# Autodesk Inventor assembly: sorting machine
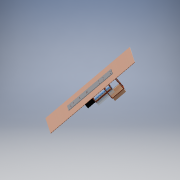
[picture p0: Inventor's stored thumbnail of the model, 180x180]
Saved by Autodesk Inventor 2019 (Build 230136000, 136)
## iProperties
Created: 2021-07
Part Number: sorting machine
Document SubType Name: Assembly
Designer: Avinash
Author: Avinash
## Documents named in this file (18)
- C:\Users\Avinash\Desktop\sorting machine\sorting machine.iam
- C:\Users\Avinash\Desktop\sorting machine\Funnel.ipt
- C:\Users\Avinash\Desktop\sorting machine\base.ipt
- C:\Users\Avinash\Desktop\sorting machine\convyour belt.ipt
- C:\Users\Avinash\Desktop\sorting machine\rotors.ipt
- C:\Users\Avinash\Desktop\sorting machine\funnel stand.ipt
- C:\Users\Avinash\Desktop\sorting machine\conveyour guard.ipt
- C:\Users\Avinash\Desktop\sorting machine\rod.ipt
- C:\Users\Avinash\Desktop\sorting machine\guard stand.ipt
- C:\Users\Avinash\Desktop\sorting machine\SENSOR BOX.ipt
- C:\Users\Avinash\Desktop\sorting machine\sensor box stand.ipt
- C:\Users\Avinash\Desktop\sorting machine\pinion ontainer.ipt
- C:\Users\Avinash\Desktop\sorting machine\rocker.ipt
- C:\Users\Avinash\Desktop\sorting machine\SERVO MOTOR.ipt
- C:\Users\Avinash\Desktop\sorting machine\BALL.ipt
- C:\Users\Avinash\Desktop\sorting machine\ultrasonic sensor.ipt
- C:\Users\Avinash\Desktop\sorting machine\control box.ipt
- C:\Users\Avinash\Desktop\sorting machine\servomotor part.ipt
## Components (22 placed, 17 different names)
1. Funnel:1 — Mate:1, Mate:2, Mate:3
2. base:1 — Flush:2, Flush:3, Flush:4, Flush:13, Mate:21, Mate:22, Flush:14, Flush:15, Flush:16, Mate:24, Flush:22, Mate:31, Flush:23, Flush:24, Flush:25, Flush:26, Flush:27, Mate:32, Flush:28, Mate:33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
3. convyour belt:1 — Flush:5, Mate:4, Flush:6, Mate:5, Mate:10, Mate:11, Mate:45, Flush:38, Mate:46, Flush:39
4. rotors:1 — Flush:6, Mate:5, Mate:6, Mate:8, Mate:12
5. rotors:2 — Flush:5, Mate:4, Mate:7, Mate:9
6. funnel stand:1 — Mate:1, Mate:2, Mate:3, Flush:2, Flush:3, Flush:4, Flush:13, Mate:21, Mate:22, Flush:14, Flush:15, Flush:16, Flush:22, Flush:25
7. conveyour guard:1 — Mate:8, Mate:9, Mate:10, Mate:18, Mate:23
8. conveyour guard:2 — Mate:6, Mate:7, Mate:11, Mate:13, Mate:14, Mate:20
9. rod:1 — Mate:12, Mate:15, Mate:17, Flush:18
10. rod:2 — Mate:13, Mate:14, Mate:16, Flush:17
11. guard stand:1 — Mate:17, Mate:18, Mate:23, Mate:24, Flush:27
12. guard stand:2 — Mate:15, Mate:16, Mate:20, Flush:17, Flush:18, Flush:26, Mate:32, Flush:28
13. SENSOR BOX:1 — Mate:26, Mate:27, Mate:40, Flush:37, Mate:50, Mate:51, Mate:52
14. sensor box stand:1 — Mate:26, Mate:27, Mate:31, Flush:23, Flush:24, Mate:33, Mate:34, Flush:29, Flush:30, Flush:31, Flush:32, Flush:42, Mate:53, Mate:54, Flush:43
15. pinion ontainer:1 — Slider:1, Flush:40, Flush:42
16. rocker:1 — Mate:35, Flush:33, Flush:34, Flush:35, Flush:36, Mate:36, Slider:1
17. SERVO MOTOR:1 — Mate:50, Mate:51, Mate:52
18. BALL:1 — Mate:45, Flush:38, Mate:46
19. ultrasonic sensor:1 — Mate:40, Flush:37
20. control box:1 — Mate:43, Mate:44
21. BALL:2 — Flush:39, Mate:47, Flush:40
22. servomotor part:1 — Mate:53, Mate:54, Flush:43
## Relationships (75: Mate 42, Flush 32, TranslationJoint 1)
- Mate:1: Funnel:1 ↔ funnel stand:1
- Mate:2: Funnel:1 ↔ funnel stand:1
- Mate:3: Funnel:1 ↔ funnel stand:1
- Flush:2: base:1 ↔ funnel stand:1
- Flush:3: base:1 ↔ funnel stand:1
- Flush:4: base:1 ↔ funnel stand:1
- Flush:5: convyour belt:1 ↔ rotors:2
- Mate:4: convyour belt:1 ↔ rotors:2
- Flush:6: convyour belt:1 ↔ rotors:1
- Mate:5: convyour belt:1 ↔ rotors:1
- Mate:6: rotors:1 ↔ conveyour guard:2
- Mate:7: rotors:2 ↔ conveyour guard:2
- Mate:8: rotors:1 ↔ conveyour guard:1
- Mate:9: rotors:2 ↔ conveyour guard:1
- Mate:10: convyour belt:1 ↔ conveyour guard:1
- Mate:11: convyour belt:1 ↔ conveyour guard:2
- Mate:12: rotors:1 ↔ rod:1
- Mate:13: conveyour guard:2 ↔ rod:2
- Mate:14: conveyour guard:2 ↔ rod:2
- Mate:15: rod:1 ↔ guard stand:2
- Mate:16: rod:2 ↔ guard stand:2
- Mate:17: rod:1 ↔ guard stand:1
- Mate:18: conveyour guard:1 ↔ guard stand:1
- Mate:20: conveyour guard:2 ↔ guard stand:2
- Flush:13: base:1 ↔ funnel stand:1
- Mate:21: base:1 ↔ funnel stand:1
- Mate:22: base:1 ↔ funnel stand:1
- Flush:14: base:1 ↔ funnel stand:1
- Flush:15: base:1 ↔ funnel stand:1
- Flush:16: base:1 ↔ funnel stand:1
- Mate:23: conveyour guard:1 ↔ guard stand:1
- Flush:17: rod:2 ↔ guard stand:2
- Flush:18: rod:1 ↔ guard stand:2
- Mate:24: base:1 ↔ guard stand:1
- Flush:22: base:1 ↔ funnel stand:1
- Mate:26: SENSOR BOX:1 ↔ sensor box stand:1
- Mate:27: SENSOR BOX:1 ↔ sensor box stand:1
- Mate:31: base:1 ↔ sensor box stand:1
- Flush:23: base:1 ↔ sensor box stand:1
- Flush:24: base:1 ↔ sensor box stand:1
- Flush:25: base:1 ↔ funnel stand:1
- Flush:26: base:1 ↔ guard stand:2
- Flush:27: base:1 ↔ guard stand:1
- Mate:32: base:1 ↔ guard stand:2
- Flush:28: base:1 ↔ guard stand:2
- Mate:33: base:1 ↔ sensor box stand:1
- Mate:34: base:1 ↔ sensor box stand:1
- Flush:29: base:1 ↔ sensor box stand:1
- Flush:30: base:1 ↔ sensor box stand:1
- Flush:31: base:1 ↔ sensor box stand:1
- Flush:32: base:1 ↔ sensor box stand:1
- Mate:35: base:1 ↔ rocker:1
- Flush:33: base:1 ↔ rocker:1
- Flush:34: base:1 ↔ rocker:1
- Flush:35: base:1 ↔ rocker:1
- Flush:36: base:1 ↔ rocker:1
- Mate:36: base:1 ↔ rocker:1
- Mate:40: SENSOR BOX:1 ↔ ultrasonic sensor:1
- Flush:37: SENSOR BOX:1 ↔ ultrasonic sensor:1
- Mate:43: base:1 ↔ control box:1
- Mate:44: base:1 ↔ control box:1
- Slider:1 [TranslationJoint]: pinion ontainer:1 ↔ rocker:1
- Mate:45: convyour belt:1 ↔ BALL:1
- Flush:38: convyour belt:1 ↔ BALL:1
- Mate:46: convyour belt:1 ↔ BALL:1
- Flush:39: convyour belt:1 ↔ BALL:2
- Mate:47: base:1 ↔ BALL:2
- Flush:40: pinion ontainer:1 ↔ BALL:2
- Mate:50: SENSOR BOX:1 ↔ SERVO MOTOR:1
- Mate:51: SENSOR BOX:1 ↔ SERVO MOTOR:1
- Mate:52: SENSOR BOX:1 ↔ SERVO MOTOR:1
- Flush:42: sensor box stand:1 ↔ pinion ontainer:1
- Mate:53: sensor box stand:1 ↔ servomotor part:1
- Mate:54: sensor box stand:1 ↔ servomotor part:1
- Flush:43: sensor box stand:1 ↔ servomotor part:1
